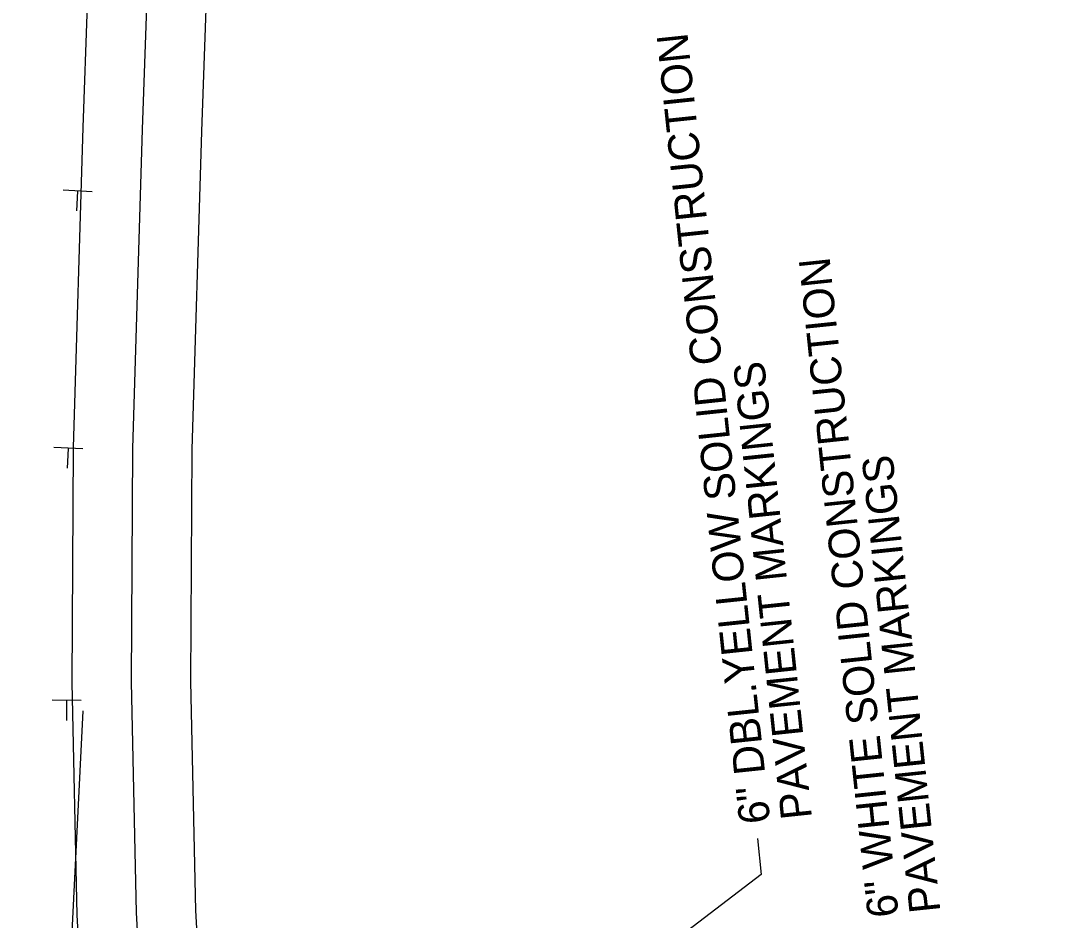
# Model space of a CAD drawing. Extents: x 633427 to 634998, y 288285 to 294065.
# Drawn here: x 634213.8 to 634413.2, y 289479 to 289653.4 of the extents above; entities that cross this region are included whole.
import ezdxf

# ---------------------------------------------------------------- set-up
doc = ezdxf.new("R2010")
doc.units = 0
for name, color, linetype in [('59', 7, 'Continuous'), ('R_Exist Surface', 7, 'Continuous'), ('S_WATER_UTILITIES', 7, 'Continuous')]:
    doc.layers.add(name, color=color, linetype=linetype)

msp = doc.modelspace()

# ---------------------------------------------------------------- linework, layer by layer
at = {"layer": '59'}
for p, q in [((634222.07, 289620.55), (634227.69, 289620.27)), ((634224.86, 289620.33), (634224.67, 289616.49)), ((634220.26, 289570.7), (634225.87, 289570.43)), ((634223.05, 289570.48), (634222.86, 289566.65)), ((634219.93, 289521.74), (634225.55, 289521.69)), ((634222.72, 289521.63), (634222.69, 289517.79))]:
    msp.add_line(p, q, dxfattribs=at)
at = {"layer": 'R_Exist Surface'}
for p, q in [((634356.63, 289494.89), (634357.36, 289487.95)), ((634357.36, 289487.95), (634242.23, 289400.18))]:
    msp.add_line(p, q, dxfattribs=at)
at = {"layer": 'S_WATER_UTILITIES'}
for points in [[(634391.43, 288835.54), (634299.68, 289105.67), (634287, 289143.77), (634268.87, 289201.35), (634256.17, 289247.97), (634250.94, 289271.34), (634245.72, 289294.71), (634243.46, 289307.36), (634241.21, 289320), (634236.7, 289345.3), (634232.84, 289377.82), (634227.32, 289434.84), (634224.79, 289480.07), (634223.78, 289525.15), (634224.08, 289570.66), (634225.94, 289632.66), (634227.62, 289680.27), (634230.44, 289750.4), (634232.4, 289798.28), (634234.34, 289845.36), (634235.37, 289868.82), (634237.56, 289923.11)], [(634402.32, 288839.23), (634310.58, 289109.34), (634297.94, 289147.31), (634279.91, 289204.59), (634267.34, 289250.73), (634262.17, 289273.85), (634256.99, 289296.97), (634254.79, 289309.37), (634252.53, 289322.02), (634248.08, 289346.99), (634244.28, 289379.05), (634238.79, 289435.72), (634236.28, 289480.52), (634235.28, 289525.24), (634235.58, 289570.45), (634237.43, 289632.28), (634239.11, 289679.83), (634241.93, 289749.93), (634243.89, 289797.81), (634245.83, 289844.87), (634246.86, 289868.34), (634249.05, 289922.64)], [(634413.21, 288842.93), (634321.48, 289113), (634308.88, 289150.85), (634290.95, 289207.83), (634278.5, 289253.5), (634273.39, 289276.36), (634268.27, 289299.24), (634266.11, 289311.39), (634263.85, 289324.04), (634259.46, 289348.67), (634255.71, 289380.29), (634250.26, 289436.59), (634247.78, 289480.97), (634246.79, 289525.33), (634247.08, 289570.24), (634248.92, 289631.91), (634250.6, 289679.4), (634253.42, 289749.47), (634255.38, 289797.34), (634257.32, 289844.38), (634258.35, 289867.86), (634260.54, 289922.18)], [(634225.87, 289519.66), (634213.8, 289276.8)]]:
    msp.add_lwpolyline(points, dxfattribs=at)

# ---------------------------------------------------------------- texts
at = {"layer": 'R_Exist Surface'}
for s, p in [('6" DBL.YELLOW SOLID CONSTRUCTION', (634359.12, 289498.06)), ('6" WHITE SOLID CONSTRUCTION', (634384.01, 289479.91)), ('PAVEMENT MARKINGS', (634367.2, 289498.91)), ('PAVEMENT MARKINGS', (634392.1, 289480.76))]:
    msp.add_text(s, height=6, rotation=96, dxfattribs=at).set_placement(p)

doc.saveas('drawing.dxf')
